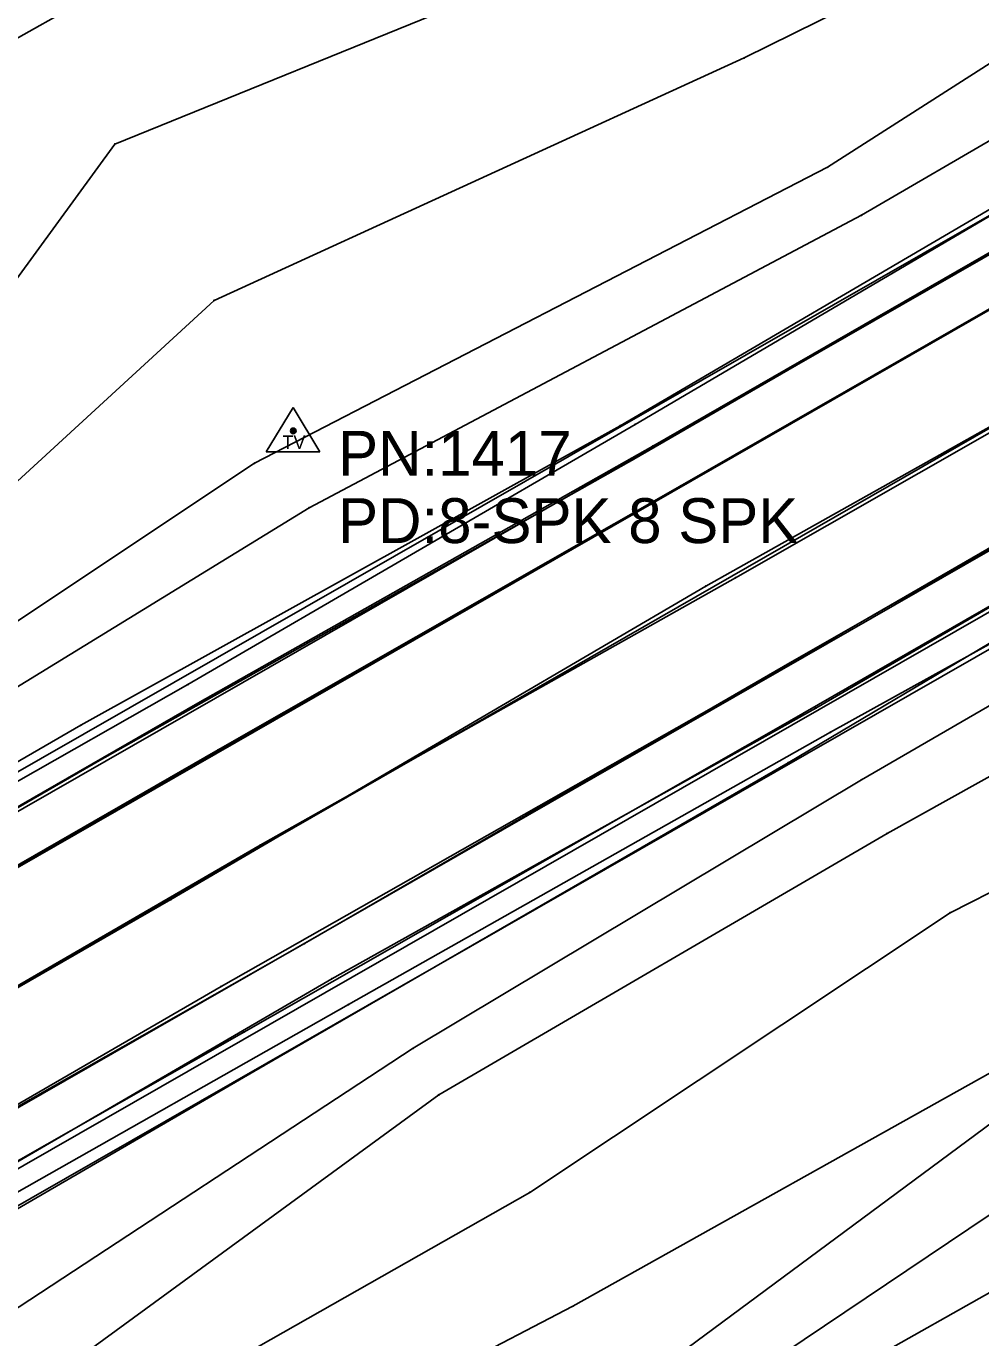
# Model space of a CAD drawing. Extents: x 1419505 to 1434054, y 1956910 to 1968644.
# Drawn here: x 1422067.1 to 1422173.5, y 1958347.6 to 1958493.7 of the extents above; entities that cross this region are included whole.
import ezdxf

# ---------------------------------------------------------------- set-up
doc = ezdxf.new("R2010")
doc.units = 0
for name, color, linetype in [('S_BREAKLINE', 7, 'Continuous'), ('S_DITCHLINE', 7, 'Continuous'), ('S_EDGE_PAVEMENT', 7, 'Continuous'), ('S_GRD_PT_SYM', 7, 'Continuous'), ('S_PAVEMENT_CROWN', 7, 'Continuous'), ('S_RDW_PT_SYM', 7, 'Continuous'), ('S_SECONDARY_CTL', 7, 'Continuous'), ('S_SECONDARY_CTL_ANNOT', 7, 'Continuous'), ('S_SHOULDER', 7, 'Continuous')]:
    doc.layers.add(name, color=color, linetype=linetype)

msp = doc.modelspace()

# ---------------------------------------------------------------- linework, layer by layer
at = {"layer": 'S_BREAKLINE'}
for p, q in [((1422063.8415, 1958491.1154), (1422155.2394, 1958542.6087)), ((1422234.7195, 1958507.1234), (1421697.9208, 1958199.8056)), ((1422076.9733, 1958480.5647), (1422140.7664, 1958506.4684)), ((1422147.1178, 1958490.1673), (1422172.3435, 1958502.6771)), ((1422156.3914, 1958477.9886), (1422181.5471, 1958494.0806)), ((1422088.028, 1958463.1556), (1422147.1178, 1958490.1673)), ((1422160.1887, 1958472.6572), (1422186.2514, 1958487.8382)), ((1422133.2899, 1958449.1747), (1422187.8885, 1958481.1578)), ((1422054.5809, 1958449.8827), (1422076.9733, 1958480.5647)), ((1422134.9521, 1958449.3267), (1422187.4834, 1958480.1927)), ((1422092.5483, 1958445.0214), (1422156.3914, 1958477.9886)), ((1422098.6307, 1958440.0531), (1422160.1887, 1958472.6572)), ((1422256.1529, 1958471.0691), (1421717.7711, 1958162.8162)), ((1422053.5668, 1958431.4825), (1422088.028, 1958463.1556)), ((1422073.1751, 1958415.8125), (1422133.2899, 1958449.1747)), ((1422085.1288, 1958420.3518), (1422134.9521, 1958449.3267)), ((1422059.3222, 1958422.91), (1422092.5483, 1958445.0214)), ((1422152.0082, 1958411.6493), (1422208.1238, 1958444.9764)), ((1422156.7455, 1958415.0575), (1422206.2847, 1958442.5003)), ((1422062.5334, 1958417.8917), (1422098.6307, 1958440.0531)), ((1422160.1877, 1958409.7551), (1422210.957, 1958439.103)), ((1422163.0459, 1958403.7638), (1422215.9603, 1958433.2477)), ((1422170.0513, 1958394.9302), (1422222.4167, 1958421.5319)), ((1422033.0325, 1958390.7609), (1422085.1288, 1958420.3518)), ((1422017.6015, 1958383.6815), (1422073.1751, 1958415.8125)), ((1422103.028, 1958384.7115), (1422156.7455, 1958415.0575)), ((1422093.6324, 1958377.9281), (1422152.0082, 1958411.6493)), ((1422110.2245, 1958379.8242), (1422160.1877, 1958409.7551)), ((1422128.0116, 1958351.0774), (1422230.2062, 1958408.28)), ((1422113.0926, 1958374.6439), (1422163.0459, 1958403.7638)), ((1422123.2103, 1958363.7582), (1422170.0513, 1958394.9302)), ((1422055.1799, 1958357.6138), (1422103.028, 1958384.7115)), ((1422063.1634, 1958348.9762), (1422110.2245, 1958379.8242)), ((1422034.6836, 1958343.7029), (1422093.6324, 1958377.9281)), ((1422068.4648, 1958342.0838), (1422113.0926, 1958374.6439)), ((1422134.688, 1958330.235), (1422201.5004, 1958367.8264)), ((1422071.824, 1958334.6333), (1422123.2103, 1958363.7582)), ((1422080.2205, 1958326.2678), (1422128.0116, 1958351.0774))]:
    msp.add_line(p, q, dxfattribs=at)
at = {"layer": 'S_DITCHLINE'}
for p, q in [((1422131.2908, 1958339.4226), (1422184.9633, 1958379.1352)), ((1422133.632, 1958333.8432), (1422193.5728, 1958374.1108))]:
    msp.add_line(p, q, dxfattribs=at)
at = {"layer": 'S_EDGE_PAVEMENT'}
for p, q in [((1422239.4358, 1958499.3739), (1421702.5421, 1958191.435)), ((1422250.9195, 1958479.1606), (1421712.8678, 1958170.5937)), ((1422137.9622, 1958441.2382), (1422192.2648, 1958472.4452)), ((1422139.9844, 1958442.4573), (1422191.4917, 1958471.9822)), ((1422148.1119, 1958420.3578), (1422203.7465, 1958452.5369)), ((1422152.2122, 1958422.78), (1422202.8354, 1958451.7399)), ((1422088.5001, 1958413.0854), (1422139.9844, 1958442.4573)), ((1422077.7144, 1958406.7339), (1422137.9622, 1958441.2382)), ((1422098.1177, 1958391.499), (1422152.2122, 1958422.78)), ((1422088.8241, 1958386.7197), (1422148.1119, 1958420.3578)), ((1422037.8508, 1958384.0085), (1422088.5001, 1958413.0854)), ((1422022.2428, 1958375.1419), (1422077.7144, 1958406.7339)), ((1422050.5066, 1958364.4322), (1422098.1177, 1958391.499)), ((1422030.9553, 1958353.2065), (1422088.8241, 1958386.7197))]:
    msp.add_line(p, q, dxfattribs=at)
at = {"layer": 'S_GRD_PT_SYM'}
for points in [[(1422147.1178, 1958490.1673), (1422147.1178, 1958490.2173), (1422147.1178, 1958490.1673), (1422147.0678, 1958490.1673), (1422147.1178, 1958490.1673), (1422147.1178, 1958490.1173), (1422147.1178, 1958490.1673), (1422147.1678, 1958490.1673)], [(1422076.9733, 1958480.5647), (1422076.9733, 1958480.6147), (1422076.9733, 1958480.5647), (1422076.9233, 1958480.5647), (1422076.9733, 1958480.5647), (1422076.9733, 1958480.5147), (1422076.9733, 1958480.5647), (1422077.0233, 1958480.5647)], [(1422156.3914, 1958477.9886), (1422156.3914, 1958478.0386), (1422156.3914, 1958477.9886), (1422156.3414, 1958477.9886), (1422156.3914, 1958477.9886), (1422156.3914, 1958477.9386), (1422156.3914, 1958477.9886), (1422156.4414, 1958477.9886)], [(1422160.1887, 1958472.6572), (1422160.1887, 1958472.7072), (1422160.1887, 1958472.6572), (1422160.1387, 1958472.6572), (1422160.1887, 1958472.6572), (1422160.1887, 1958472.6072), (1422160.1887, 1958472.6572), (1422160.2387, 1958472.6572)], [(1422088.028, 1958463.1556), (1422088.028, 1958463.2056), (1422088.028, 1958463.1556), (1422087.978, 1958463.1556), (1422088.028, 1958463.1556), (1422088.028, 1958463.1056), (1422088.028, 1958463.1556), (1422088.078, 1958463.1556)], [(1422133.2899, 1958449.1747), (1422133.2899, 1958449.2247), (1422133.2899, 1958449.1747), (1422133.2399, 1958449.1747), (1422133.2899, 1958449.1747), (1422133.2899, 1958449.1247), (1422133.2899, 1958449.1747), (1422133.3399, 1958449.1747)], [(1422134.9521, 1958449.3267), (1422134.9521, 1958449.3767), (1422134.9521, 1958449.3267), (1422134.9021, 1958449.3267), (1422134.9521, 1958449.3267), (1422134.9521, 1958449.2767), (1422134.9521, 1958449.3267), (1422135.0021, 1958449.3267)], [(1422092.5483, 1958445.0214), (1422092.5483, 1958445.0714), (1422092.5483, 1958445.0214), (1422092.4983, 1958445.0214), (1422092.5483, 1958445.0214), (1422092.5483, 1958444.9714), (1422092.5483, 1958445.0214), (1422092.5983, 1958445.0214)], [(1422098.6307, 1958440.0531), (1422098.6307, 1958440.1031), (1422098.6307, 1958440.0531), (1422098.5807, 1958440.0531), (1422098.6307, 1958440.0531), (1422098.6307, 1958440.0031), (1422098.6307, 1958440.0531), (1422098.6807, 1958440.0531)], [(1422085.1288, 1958420.3518), (1422085.1288, 1958420.4018), (1422085.1288, 1958420.3518), (1422085.0788, 1958420.3518), (1422085.1288, 1958420.3518), (1422085.1288, 1958420.3018), (1422085.1288, 1958420.3518), (1422085.1788, 1958420.3518)], [(1422073.1751, 1958415.8125), (1422073.1751, 1958415.8625), (1422073.1751, 1958415.8125), (1422073.1251, 1958415.8125), (1422073.1751, 1958415.8125), (1422073.1751, 1958415.7625), (1422073.1751, 1958415.8125), (1422073.2251, 1958415.8125)], [(1422156.7455, 1958415.0575), (1422156.7455, 1958415.1075), (1422156.7455, 1958415.0575), (1422156.6955, 1958415.0575), (1422156.7455, 1958415.0575), (1422156.7455, 1958415.0075), (1422156.7455, 1958415.0575), (1422156.7955, 1958415.0575)], [(1422152.0082, 1958411.6493), (1422152.0082, 1958411.6993), (1422152.0082, 1958411.6493), (1422151.9582, 1958411.6493), (1422152.0082, 1958411.6493), (1422152.0082, 1958411.5993), (1422152.0082, 1958411.6493), (1422152.0582, 1958411.6493)], [(1422160.1877, 1958409.7551), (1422160.1877, 1958409.8051), (1422160.1877, 1958409.7551), (1422160.1377, 1958409.7551), (1422160.1877, 1958409.7551), (1422160.1877, 1958409.7051), (1422160.1877, 1958409.7551), (1422160.2377, 1958409.7551)], [(1422163.0459, 1958403.7638), (1422163.0459, 1958403.8138), (1422163.0459, 1958403.7638), (1422162.9959, 1958403.7638), (1422163.0459, 1958403.7638), (1422163.0459, 1958403.7138), (1422163.0459, 1958403.7638), (1422163.0959, 1958403.7638)], [(1422170.0513, 1958394.9302), (1422170.0513, 1958394.9802), (1422170.0513, 1958394.9302), (1422170.0013, 1958394.9302), (1422170.0513, 1958394.9302), (1422170.0513, 1958394.8802), (1422170.0513, 1958394.9302), (1422170.1013, 1958394.9302)], [(1422103.028, 1958384.7115), (1422103.028, 1958384.7615), (1422103.028, 1958384.7115), (1422102.978, 1958384.7115), (1422103.028, 1958384.7115), (1422103.028, 1958384.6615), (1422103.028, 1958384.7115), (1422103.078, 1958384.7115)], [(1422110.2245, 1958379.8242), (1422110.2245, 1958379.8742), (1422110.2245, 1958379.8242), (1422110.1745, 1958379.8242), (1422110.2245, 1958379.8242), (1422110.2245, 1958379.7742), (1422110.2245, 1958379.8242), (1422110.2745, 1958379.8242)], [(1422093.6324, 1958377.9281), (1422093.6324, 1958377.9781), (1422093.6324, 1958377.9281), (1422093.5824, 1958377.9281), (1422093.6324, 1958377.9281), (1422093.6324, 1958377.8781), (1422093.6324, 1958377.9281), (1422093.6824, 1958377.9281)], [(1422113.0926, 1958374.6439), (1422113.0926, 1958374.6939), (1422113.0926, 1958374.6439), (1422113.0426, 1958374.6439), (1422113.0926, 1958374.6439), (1422113.0926, 1958374.5939), (1422113.0926, 1958374.6439), (1422113.1426, 1958374.6439)], [(1422123.2103, 1958363.7582), (1422123.2103, 1958363.8082), (1422123.2103, 1958363.7582), (1422123.1603, 1958363.7582), (1422123.2103, 1958363.7582), (1422123.2103, 1958363.7082), (1422123.2103, 1958363.7582), (1422123.2603, 1958363.7582)], [(1422128.0116, 1958351.0774), (1422128.0116, 1958351.1274), (1422128.0116, 1958351.0774), (1422127.9616, 1958351.0774), (1422128.0116, 1958351.0774), (1422128.0116, 1958351.0274), (1422128.0116, 1958351.0774), (1422128.0616, 1958351.0774)]]:
    msp.add_lwpolyline(points, dxfattribs=at)
at = {"layer": 'S_PAVEMENT_CROWN'}
for p, q in [((1422245.2512, 1958489.5463), (1421708.2975, 1958181.3584)), ((1422142.8236, 1958431.3225), (1422197.6671, 1958462.0865)), ((1422146.1268, 1958432.2546), (1422197.1311, 1958461.3425)), ((1422083.2277, 1958396.4123), (1422142.8236, 1958431.3225)), ((1422093.1814, 1958402.4757), (1422146.1268, 1958432.2546)), ((1422043.7072, 1958373.7848), (1422093.1814, 1958402.4757)), ((1422026.7281, 1958363.9952), (1422083.2277, 1958396.4123))]:
    msp.add_line(p, q, dxfattribs=at)
at = {"layer": 'S_RDW_PT_SYM'}
for points in [[(1422136.9252, 1958446.9125), (1422136.9252, 1958446.9625), (1422136.9252, 1958446.9125), (1422136.8752, 1958446.9125), (1422136.9252, 1958446.9125), (1422136.9252, 1958446.8625), (1422136.9252, 1958446.9125), (1422136.9752, 1958446.9125)], [(1422134.806, 1958445.4775), (1422134.806, 1958445.5275), (1422134.806, 1958445.4775), (1422134.756, 1958445.4775), (1422134.806, 1958445.4775), (1422134.806, 1958445.4275), (1422134.806, 1958445.4775), (1422134.856, 1958445.4775)], [(1422139.9844, 1958442.4573), (1422139.9844, 1958442.5073), (1422139.9844, 1958442.4573), (1422139.9344, 1958442.4573), (1422139.9844, 1958442.4573), (1422139.9844, 1958442.4073), (1422139.9844, 1958442.4573), (1422140.0344, 1958442.4573)], [(1422137.9622, 1958441.2382), (1422137.9622, 1958441.2882), (1422137.9622, 1958441.2382), (1422137.9122, 1958441.2382), (1422137.9622, 1958441.2382), (1422137.9622, 1958441.1882), (1422137.9622, 1958441.2382), (1422138.0122, 1958441.2382)], [(1422142.8236, 1958431.3225), (1422142.8236, 1958431.3725), (1422142.8236, 1958431.3225), (1422142.7736, 1958431.3225), (1422142.8236, 1958431.3225), (1422142.8236, 1958431.2725), (1422142.8236, 1958431.3225), (1422142.8736, 1958431.3225)], [(1422146.1268, 1958432.2546), (1422146.1268, 1958432.3046), (1422146.1268, 1958432.2546), (1422146.0768, 1958432.2546), (1422146.1268, 1958432.2546), (1422146.1268, 1958432.2046), (1422146.1268, 1958432.2546), (1422146.1768, 1958432.2546)], [(1422152.2122, 1958422.78), (1422152.2122, 1958422.83), (1422152.2122, 1958422.78), (1422152.1622, 1958422.78), (1422152.2122, 1958422.78), (1422152.2122, 1958422.73), (1422152.2122, 1958422.78), (1422152.2622, 1958422.78)], [(1422148.1119, 1958420.3578), (1422148.1119, 1958420.4078), (1422148.1119, 1958420.3578), (1422148.0619, 1958420.3578), (1422148.1119, 1958420.3578), (1422148.1119, 1958420.3078), (1422148.1119, 1958420.3578), (1422148.1619, 1958420.3578)], [(1422086.2219, 1958418.2657), (1422086.2219, 1958418.3157), (1422086.2219, 1958418.2657), (1422086.1719, 1958418.2657), (1422086.2219, 1958418.2657), (1422086.2219, 1958418.2157), (1422086.2219, 1958418.2657), (1422086.2719, 1958418.2657)], [(1422155.0904, 1958417.7157), (1422155.0904, 1958417.7657), (1422155.0904, 1958417.7157), (1422155.0404, 1958417.7157), (1422155.0904, 1958417.7157), (1422155.0904, 1958417.6657), (1422155.0904, 1958417.7157), (1422155.1404, 1958417.7157)], [(1422150.4291, 1958415.2545), (1422150.4291, 1958415.3045), (1422150.4291, 1958415.2545), (1422150.3791, 1958415.2545), (1422150.4291, 1958415.2545), (1422150.4291, 1958415.2045), (1422150.4291, 1958415.2545), (1422150.4791, 1958415.2545)], [(1422088.5001, 1958413.0854), (1422088.5001, 1958413.1354), (1422088.5001, 1958413.0854), (1422088.4501, 1958413.0854), (1422088.5001, 1958413.0854), (1422088.5001, 1958413.0354), (1422088.5001, 1958413.0854), (1422088.5501, 1958413.0854)], [(1422075.2692, 1958411.9093), (1422075.2692, 1958411.9593), (1422075.2692, 1958411.9093), (1422075.2192, 1958411.9093), (1422075.2692, 1958411.9093), (1422075.2692, 1958411.8593), (1422075.2692, 1958411.9093), (1422075.3192, 1958411.9093)], [(1422077.7144, 1958406.7339), (1422077.7144, 1958406.7839), (1422077.7144, 1958406.7339), (1422077.6644, 1958406.7339), (1422077.7144, 1958406.7339), (1422077.7144, 1958406.6839), (1422077.7144, 1958406.7339), (1422077.7644, 1958406.7339)], [(1422093.1814, 1958402.4757), (1422093.1814, 1958402.5257), (1422093.1814, 1958402.4757), (1422093.1314, 1958402.4757), (1422093.1814, 1958402.4757), (1422093.1814, 1958402.4257), (1422093.1814, 1958402.4757), (1422093.2314, 1958402.4757)], [(1422083.2277, 1958396.4123), (1422083.2277, 1958396.4623), (1422083.2277, 1958396.4123), (1422083.1777, 1958396.4123), (1422083.2277, 1958396.4123), (1422083.2277, 1958396.3623), (1422083.2277, 1958396.4123), (1422083.2777, 1958396.4123)], [(1422098.1177, 1958391.499), (1422098.1177, 1958391.549), (1422098.1177, 1958391.499), (1422098.0677, 1958391.499), (1422098.1177, 1958391.499), (1422098.1177, 1958391.449), (1422098.1177, 1958391.499), (1422098.1677, 1958391.499)], [(1422101.1489, 1958387.5657), (1422101.1489, 1958387.6157), (1422101.1489, 1958387.5657), (1422101.0989, 1958387.5657), (1422101.1489, 1958387.5657), (1422101.1489, 1958387.5157), (1422101.1489, 1958387.5657), (1422101.1989, 1958387.5657)], [(1422088.8241, 1958386.7197), (1422088.8241, 1958386.7697), (1422088.8241, 1958386.7197), (1422088.7741, 1958386.7197), (1422088.8241, 1958386.7197), (1422088.8241, 1958386.6697), (1422088.8241, 1958386.7197), (1422088.8741, 1958386.7197)], [(1422091.3382, 1958381.6133), (1422091.3382, 1958381.6633), (1422091.3382, 1958381.6133), (1422091.2882, 1958381.6133), (1422091.3382, 1958381.6133), (1422091.3382, 1958381.5633), (1422091.3382, 1958381.6133), (1422091.3882, 1958381.6133)]]:
    msp.add_lwpolyline(points, dxfattribs=at)
at = {"layer": 'S_SECONDARY_CTL'}
for p, q in [((1422096.8616, 1958451.2298), (1422093.8516, 1958446.2759)), ((1422096.8616, 1958451.2298), (1422099.8089, 1958446.2759)), ((1422093.8516, 1958446.2759), (1422099.8089, 1958446.2759))]:
    msp.add_line(p, q, dxfattribs=at)
for radius in [0.3111, 0.1827, 0.1033]:
    msp.add_circle((1422096.8616, 1958448.6197), radius, dxfattribs=at)
at = {"layer": 'S_SHOULDER'}
for p, q in [((1422236.8876, 1958504.0772), (1421699.4589, 1958196.0923)), ((1422134.806, 1958445.4775), (1422190.1426, 1958477.4545)), ((1422136.9252, 1958446.9125), (1422189.0865, 1958476.9025)), ((1422254.1918, 1958474.1573), (1421715.306, 1958165.4004)), ((1422150.4291, 1958415.2545), (1422206.5097, 1958447.5796)), ((1422086.2219, 1958418.2657), (1422136.9252, 1958446.9125)), ((1422155.0904, 1958417.7157), (1422204.8096, 1958446.6245)), ((1422075.2692, 1958411.9093), (1422134.806, 1958445.4775)), ((1422034.6106, 1958388.6498), (1422086.2219, 1958418.2657)), ((1422101.1489, 1958387.5657), (1422155.0904, 1958417.7157)), ((1422091.3382, 1958381.6133), (1422150.4291, 1958415.2545)), ((1422019.2166, 1958379.5102), (1422075.2692, 1958411.9093)), ((1422053.6768, 1958359.9559), (1422101.1489, 1958387.5657)), ((1422032.1004, 1958347.9462), (1422091.3382, 1958381.6133))]:
    msp.add_line(p, q, dxfattribs=at)

# ---------------------------------------------------------------- texts
at = {"layer": 'S_SECONDARY_CTL'}
msp.add_text('TV', height=1.5, rotation=360, dxfattribs=at).set_placement((1422095.6569, 1958446.6084))
at = {"layer": 'S_SECONDARY_CTL_ANNOT'}
for s, p in [('PN:1417', (1422101.8616, 1958443.6197)), ('PD:8-SPK 8 SPK', (1422101.8616, 1958436.1197))]:
    msp.add_text(s, height=5, dxfattribs=at).set_placement(p)

doc.saveas('drawing.dxf')
